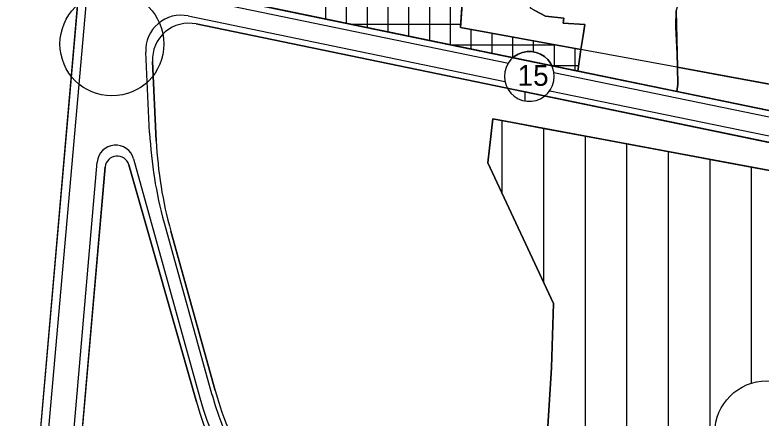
# Model space of a CAD drawing. Extents: x 427903 to 430077, y 4477233 to 4480385.
# Drawn here: x 428375.8 to 428734.8, y 4477497.4 to 4477691.4 of the extents above; entities that cross this region are included whole.
import ezdxf

# ---------------------------------------------------------------- set-up
doc = ezdxf.new("R2010")
doc.units = 0
for name, color, linetype in [('ADAKENARI', 7, 'Continuous'), ('KALDIRIM', 7, 'Continuous'), ('KD_DAIRE', 7, 'Continuous'), ('KD_KAV_DA', 7, 'Continuous'), ('KD_YGEN', 7, 'Continuous'), ('PL_K_TALI_IS_MRK', 7, 'Continuous'), ('PL_KON_MEV_150', 7, 'Continuous'), ('PL_SAY_ILKOGRETIM', 7, 'Continuous'), ('SM_DAIRE', 7, 'Continuous'), ('TR_AZYOGUNKONUT', 7, 'Continuous'), ('TR_ILKEGITIM', 7, 'Continuous'), ('TR_TALIISMERK', 7, 'Continuous')]:
    doc.layers.add(name, color=color, linetype=linetype)

msp = doc.modelspace()

# ---------------------------------------------------------------- linework, layer by layer
at = {"layer": 'ADAKENARI'}
for p, q in [((428590.12, 4477685.46), (428594.74, 4477750.3)), ((428408.85, 4477729.21), (428366.87, 4477249.22)), ((428847.06, 4477622.99), (428441.36, 4477706.89)), ((428463.01, 4477687.09), (428615.63, 4477655.53)), ((428860.4, 4477635.66), (428590.12, 4477685.46)), ((428443.79, 4477630.84), (428441.95, 4477669.09)), ((428615.63, 4477655.53), (428924.99, 4477591.56)), ((428621.21, 4477650.07), (428621.21, 4477654.39)), ((428605.75, 4477641.43), (428603.35, 4477620.21)), ((428857.27, 4477594.38), (428605.75, 4477641.43)), ((428393.23, 4477321.12), (428419.22, 4477618.28)), ((428430.55, 4477619.3), (428463.11, 4477505.16)), ((428603.35, 4477620.21), (428634.94, 4477552.53)), ((428472.13, 4477510.61), (428450.8, 4477587.3)), ((428634.94, 4477552.53), (428633.92, 4477521.77)), ((428633.92, 4477521.77), (428630.48, 4477467.61))]:
    msp.add_line(p, q, dxfattribs=at)
msp.add_lwpolyline([(428693.89, 4477693.57), (428694.48, 4477666.23), (428694.67, 4477657.98), (428694.17, 4477654.61), (428646.58, 4477664.45), (428649.9, 4477686.86), (428639.49, 4477687.53), (428639.8, 4477689.85), (428631.05, 4477690.89), (428623.78, 4477694.62)], dxfattribs=at)
for centre, radius, start, end in [((428459.46, 4477669.93), 17.53, 78.3166, 182.7499), ((428641.48, 4477640.33), 197.92, 182.7499, 195.5411), ((428424.98, 4477617.78), 5.78, 15.2172, 175.0016), ((428629.69, 4477554.43), 163.54, 195.5411, 255.6258), ((428626.98, 4477551.89), 170.41, 195.9184, 255.6258)]:
    msp.add_arc(centre, radius, start, end, dxfattribs=at)
at = {"layer": 'KALDIRIM'}
for p, q in [((428387.85, 4477443.16), (428412.89, 4477729.53)), ((428437.16, 4477704.69), (428613.16, 4477668.3)), ((428459.16, 4477690.95), (428611.51, 4477659.45)), ((428440.6, 4477634.76), (428438.74, 4477673.49)), ((428635.12, 4477663.75), (428849.48, 4477619.43)), ((428633.12, 4477654.98), (428925.59, 4477594.5)), ((428432.87, 4477622.2), (428464.81, 4477507.1)), ((428399.73, 4477441.27), (428415.42, 4477620.64)), ((428447.57, 4477591.44), (428470.59, 4477508.66))]:
    msp.add_line(p, q, dxfattribs=at)
for centre, radius, start, end in [((428455.72, 4477674.3), 17, 78.3166, 182.7499), ((428637.36, 4477644.22), 196.99, 182.7499, 195.5411), ((428424.28, 4477619.87), 8.9, 15.2172, 175.0016), ((428627.59, 4477552.28), 168.93, 195.5098, 255.6258), ((428627.63, 4477552.33), 162.99, 195.5411, 255.6258)]:
    msp.add_arc(centre, radius, start, end, dxfattribs=at)
at = {"layer": 'KD_DAIRE'}
for p, q in [((428616.04, 4477671.42), (428614.4, 4477669.93)), ((428616.04, 4477671.42), (428614.4, 4477669.93)), ((428617.92, 4477672.58), (428616.04, 4477671.42)), ((428617.92, 4477672.58), (428616.04, 4477671.42)), ((428619.99, 4477673.38), (428617.92, 4477672.58)), ((428619.99, 4477673.38), (428617.92, 4477672.58)), ((428622.16, 4477673.79), (428619.99, 4477673.38)), ((428622.16, 4477673.79), (428619.99, 4477673.38)), ((428624.38, 4477673.79), (428622.16, 4477673.79)), ((428624.38, 4477673.79), (428622.16, 4477673.79)), ((428626.56, 4477673.38), (428624.38, 4477673.79)), ((428626.56, 4477673.38), (428624.38, 4477673.79)), ((428628.62, 4477672.58), (428626.56, 4477673.38)), ((428628.62, 4477672.58), (428626.56, 4477673.38)), ((428630.5, 4477671.42), (428628.62, 4477672.58)), ((428630.5, 4477671.42), (428628.62, 4477672.58)), ((428632.14, 4477669.93), (428630.5, 4477671.42)), ((428632.14, 4477669.93), (428630.5, 4477671.42)), ((428613.07, 4477668.16), (428612.08, 4477666.18)), ((428613.07, 4477668.16), (428612.08, 4477666.18)), ((428614.4, 4477669.93), (428613.07, 4477668.16)), ((428614.4, 4477669.93), (428613.07, 4477668.16)), ((428633.47, 4477668.16), (428632.14, 4477669.93)), ((428633.47, 4477668.16), (428632.14, 4477669.93)), ((428634.46, 4477666.18), (428633.47, 4477668.16)), ((428634.46, 4477666.18), (428633.47, 4477668.16)), ((428611.48, 4477664.05), (428611.27, 4477661.84)), ((428611.48, 4477664.05), (428611.27, 4477661.84)), ((428612.08, 4477666.18), (428611.48, 4477664.05)), ((428612.08, 4477666.18), (428611.48, 4477664.05)), ((428635.07, 4477664.05), (428634.46, 4477666.18)), ((428635.07, 4477664.05), (428634.46, 4477666.18)), ((428635.27, 4477661.84), (428635.07, 4477664.05)), ((428635.27, 4477661.84), (428635.07, 4477664.05)), ((428611.27, 4477661.84), (428611.48, 4477659.64)), ((428611.27, 4477661.84), (428611.48, 4477659.64)), ((428635.07, 4477659.64), (428635.27, 4477661.84)), ((428635.07, 4477659.64), (428635.27, 4477661.84)), ((428635.27, 4477661.84), (428635.27, 4477661.84)), ((428635.27, 4477661.84), (428635.27, 4477661.84)), ((428611.48, 4477659.64), (428612.08, 4477657.51)), ((428611.48, 4477659.64), (428612.08, 4477657.51)), ((428612.08, 4477657.51), (428613.07, 4477655.52)), ((428612.08, 4477657.51), (428613.07, 4477655.52)), ((428633.47, 4477655.52), (428634.46, 4477657.51)), ((428633.47, 4477655.52), (428634.46, 4477657.51)), ((428634.46, 4477657.51), (428635.07, 4477659.64)), ((428634.46, 4477657.51), (428635.07, 4477659.64)), ((428613.07, 4477655.52), (428614.4, 4477653.76)), ((428613.07, 4477655.52), (428614.4, 4477653.76)), ((428614.4, 4477653.76), (428616.04, 4477652.26)), ((428614.4, 4477653.76), (428616.04, 4477652.26)), ((428630.5, 4477652.26), (428632.14, 4477653.76)), ((428630.5, 4477652.26), (428632.14, 4477653.76)), ((428632.14, 4477653.76), (428633.47, 4477655.52)), ((428632.14, 4477653.76), (428633.47, 4477655.52)), ((428616.04, 4477652.26), (428617.92, 4477651.1)), ((428616.04, 4477652.26), (428617.92, 4477651.1)), ((428617.92, 4477651.1), (428619.99, 4477650.3)), ((428617.92, 4477651.1), (428619.99, 4477650.3)), ((428619.99, 4477650.3), (428622.16, 4477649.89)), ((428619.99, 4477650.3), (428622.16, 4477649.89)), ((428622.16, 4477649.89), (428624.38, 4477649.89)), ((428622.16, 4477649.89), (428624.38, 4477649.89)), ((428624.38, 4477649.89), (428626.56, 4477650.3)), ((428624.38, 4477649.89), (428626.56, 4477650.3)), ((428626.56, 4477650.3), (428628.62, 4477651.1)), ((428626.56, 4477650.3), (428628.62, 4477651.1)), ((428628.62, 4477651.1), (428630.5, 4477652.26)), ((428628.62, 4477651.1), (428630.5, 4477652.26))]:
    msp.add_line(p, q, dxfattribs=at)
at = {"layer": 'KD_KAV_DA'}
msp.add_circle((428422.47, 4477677.46), 25, dxfattribs=at)
at = {"layer": 'PL_K_TALI_IS_MRK'}
for points in [[(428441.36, 4477706.89), (428646.58, 4477664.45), (428648.09, 4477674.78), (428590.12, 4477685.46), (428594.74, 4477750.3), (428634.75, 4477751.63), (428636.08, 4477763.84), (428674.99, 4477765.93), (428678.2, 4477753.08), (428763.81, 4477755.92), (428875.07, 4477746.86), (428860.4, 4477635.66), (428694.48, 4477666.23), (428694.67, 4477657.98)], [(428366.87, 4477249.22), (428408.85, 4477729.21)], [(428891.92, 4477420.61), (428878.39, 4477421.75), (428877.77, 4477465.86), (428888.48, 4477466.51), (428892.66, 4477466.82), (428893.57, 4477524.11), (428893.84, 4477540.99), (428894.12, 4477558.47), (428883.39, 4477557.49), (428886.38, 4477599.54), (428621.21, 4477654.38), (428621.21, 4477654.38), (428615.63, 4477655.53), (428463.01, 4477687.09)], [(428441.95, 4477669.09), (428443.79, 4477630.84)], [(428694.67, 4477657.98), (428694.17, 4477654.61), (428847.06, 4477622.99)], [(428630.48, 4477467.61), (428633.92, 4477521.77), (428634.94, 4477552.53), (428630.22, 4477562.63), (428610.22, 4477605.48), (428603.35, 4477620.21), (428605.75, 4477641.43), (428610.22, 4477640.59), (428630.22, 4477636.85), (428650.22, 4477633.11), (428670.22, 4477629.37), (428690.22, 4477625.63)], [(428690.22, 4477625.63), (428710.22, 4477621.89), (428730.22, 4477618.14), (428750.22, 4477614.4), (428770.22, 4477610.66), (428790.22, 4477606.92), (428810.22, 4477603.18), (428830.22, 4477599.44), (428850.22, 4477595.7), (428857.27, 4477594.38), (428851.24, 4477498.49), (428850.22, 4477498.5), (428839.52, 4477498.6), (428838.69, 4477488.35)], [(428419.22, 4477618.28), (428393.23, 4477321.12), (428408.87, 4477320.97), (428411.96, 4477335.09), (428452.28, 4477328.86), (428493.21, 4477322.54), (428483.34, 4477275.45), (428509.85, 4477272.85), (428505.83, 4477247.86)], [(428463.11, 4477505.16), (428430.55, 4477619.3)], [(428450.8, 4477587.3), (428472.13, 4477510.61)]]:
    msp.add_lwpolyline(points, dxfattribs=at)
for centre, radius, start, end in [((428459.46, 4477669.93), 17.53, 78.3166, 182.7499), ((428641.48, 4477640.33), 197.92, 182.7499, 195.5411), ((428424.98, 4477617.78), 5.78, 15.2172, 175.0016), ((428629.69, 4477554.43), 163.54, 195.5411, 255.6258), ((428626.98, 4477551.89), 170.41, 195.9184, 255.6258)]:
    msp.add_arc(centre, radius, start, end, dxfattribs=at)
at = {"layer": 'PL_KON_MEV_150'}
for points in [[(428648.09, 4477674.78), (428649.09, 4477681.58), (428649.9, 4477686.86), (428639.49, 4477687.53), (428639.8, 4477689.85), (428631.05, 4477690.89), (428625.57, 4477693.67), (428623.78, 4477694.62), (428629.92, 4477721.31), (428631.49, 4477729.18), (428633.6, 4477742.79), (428634.43, 4477748.66), (428634.75, 4477751.63), (428594.74, 4477750.3), (428590.12, 4477685.46), (428648.09, 4477674.78)], [(428693.89, 4477693.57), (428694.48, 4477666.23), (428711.71, 4477663.06), (428731.71, 4477659.37), (428751.71, 4477655.69)]]:
    msp.add_lwpolyline(points, dxfattribs=at)
msp.add_lwpolyline([(428857.27, 4477594.38), (428851.24, 4477498.49), (428839.52, 4477498.6), (428838.69, 4477488.35), (428855.47, 4477480.87), (428852.32, 4477379.82), (428847.13, 4477374.01), (428765.15, 4477379.18), (428757.18, 4477388.77), (428744.71, 4477386.69), (428724.03, 4477368.58), (428691.7, 4477357.89), (428668.48, 4477380.82), (428635.65, 4477394.31), (428637.38, 4477422.86), (428644.03, 4477428.66), (428637.63, 4477449.23), (428630.48, 4477467.61), (428633.92, 4477521.77), (428634.94, 4477552.53), (428603.35, 4477620.21), (428605.75, 4477641.43)], close=True, dxfattribs=at)
at = {"layer": 'PL_SAY_ILKOGRETIM'}
for points in [[(428625.57, 4477693.67), (428631.05, 4477690.89), (428639.8, 4477689.85), (428639.49, 4477687.53), (428649.9, 4477686.86), (428649.09, 4477681.58), (428648.09, 4477674.78), (428646.58, 4477664.45), (428694.17, 4477654.61), (428694.67, 4477657.98), (428694.48, 4477666.23)], [(428694.48, 4477666.23), (428694.32, 4477672.65), (428693.75, 4477685.63), (428693.89, 4477693.57)]]:
    msp.add_lwpolyline(points, dxfattribs=at)
at = {"layer": 'SM_DAIRE'}
msp.add_circle((428737.52, 4477490.34), 25, dxfattribs=at)
at = {"layer": 'TR_AZYOGUNKONUT'}
for p, q in [((428610.22, 4477605.48), (428610.22, 4477640.59)), ((428630.22, 4477562.63), (428630.22, 4477636.85)), ((428650.22, 4477388.32), (428650.22, 4477633.11)), ((428670.22, 4477379.1), (428670.22, 4477629.37)), ((428690.22, 4477359.36), (428690.22, 4477625.63)), ((428710.22, 4477364.01), (428710.22, 4477621.89)), ((428730.22, 4477514.26), (428730.22, 4477618.14))]:
    msp.add_line(p, q, dxfattribs=at)
for points in [[(428763.81, 4477755.92), (428678.2, 4477753.08), (428678.39, 4477752.31), (428691.89, 4477752.29), (428700.09, 4477751.33), (428710.89, 4477750.43), (428720.87, 4477749.84), (428733.52, 4477748.79), (428733.74, 4477745.65), (428734.17, 4477745.55), (428734.17, 4477741.2), (428730.29, 4477734.01), (428722.14, 4477721.74), (428725.06, 4477715.86), (428729.23, 4477707.26), (428717.2, 4477706.36), (428707.78, 4477705.66), (428697.15, 4477704.92), (428693.89, 4477693.57), (428693.75, 4477685.63), (428694.32, 4477672.65), (428694.48, 4477666.23), (428854.98, 4477636.65)], [(428441.36, 4477706.89), (428615.46, 4477670.88), (428616.04, 4477671.42), (428617.92, 4477672.58), (428619.99, 4477673.38), (428622.16, 4477673.79), (428624.38, 4477673.79), (428626.56, 4477673.38), (428628.62, 4477672.58), (428630.5, 4477671.42), (428632.14, 4477669.93), (428633.47, 4477668.16), (428634.03, 4477667.04), (428646.58, 4477664.45), (428648.09, 4477674.78), (428590.12, 4477685.46), (428594.74, 4477750.3)], [(428594.74, 4477750.3), (428590.12, 4477685.46), (428648.09, 4477674.78), (428649.09, 4477681.58), (428649.9, 4477686.86), (428639.49, 4477687.53), (428639.8, 4477689.85), (428631.05, 4477690.89), (428625.57, 4477693.67), (428623.78, 4477694.62), (428629.92, 4477721.31), (428631.49, 4477729.18), (428633.6, 4477742.79), (428634.43, 4477748.66), (428634.75, 4477751.63), (428594.74, 4477750.3)], [(428693.89, 4477693.57), (428694.48, 4477666.23), (428711.71, 4477663.06), (428731.71, 4477659.37), (428751.71, 4477655.69)], [(428691.7, 4477357.89), (428724.03, 4477368.58), (428744.71, 4477386.69), (428757.18, 4477388.77), (428765.15, 4477379.18), (428847.13, 4477374.01), (428852.32, 4477379.82), (428855.47, 4477480.87), (428838.69, 4477488.35), (428839.52, 4477498.6), (428851.24, 4477498.49), (428857.27, 4477594.38), (428605.75, 4477641.43), (428603.35, 4477620.21), (428634.94, 4477552.53), (428633.92, 4477521.77), (428630.48, 4477467.61), (428637.63, 4477449.23), (428644.03, 4477428.66), (428637.38, 4477422.86), (428635.65, 4477394.31), (428668.48, 4477380.82), (428691.7, 4477357.89)]]:
    msp.add_lwpolyline(points, dxfattribs=at)
at = {"layer": 'TR_ILKEGITIM'}
for p, q in [((428662.86, 4477672.3), (428662.86, 4477672.3)), ((428662.86, 4477672.3), (428662.86, 4477672.3)), ((428682.86, 4477672.3), (428682.86, 4477672.3)), ((428682.86, 4477672.3), (428682.86, 4477672.3))]:
    msp.add_line(p, q, dxfattribs=at)
at = {"layer": 'TR_TALIISMERK'}
for p, q in [((428535.33, 4477687.45), (428535.33, 4477920.37)), ((428545.33, 4477685.39), (428545.33, 4477918.52)), ((428555.33, 4477683.32), (428555.33, 4477916.66)), ((428565.33, 4477681.25), (428565.33, 4477914.81)), ((428575.33, 4477679.18), (428575.33, 4477912.95)), ((428585.33, 4477677.11), (428585.33, 4477911.09)), ((428525.33, 4477689.52), (428525.33, 4477813.49)), ((428590.22, 4477686.9), (428537.98, 4477686.9)), ((428595.33, 4477675.05), (428595.33, 4477684.5)), ((428605.33, 4477672.98), (428605.33, 4477682.66)), ((428615.33, 4477670.91), (428615.33, 4477680.82)), ((428625.33, 4477673.61), (428625.33, 4477678.97)), ((428636.56, 4477676.9), (428586.34, 4477676.9)), ((428635.33, 4477666.77), (428635.33, 4477677.13)), ((428645.33, 4477664.71), (428645.33, 4477675.29)), ((428646.94, 4477666.9), (428634.7, 4477666.9))]:
    msp.add_line(p, q, dxfattribs=at)
for points in [[(428441.36, 4477706.89), (428615.46, 4477670.88), (428616.04, 4477671.42), (428617.92, 4477672.58), (428619.99, 4477673.38), (428622.16, 4477673.79), (428624.38, 4477673.79), (428626.56, 4477673.38), (428628.62, 4477672.58), (428630.5, 4477671.42), (428632.14, 4477669.93), (428633.47, 4477668.16), (428634.03, 4477667.04), (428646.58, 4477664.45), (428648.09, 4477674.78), (428590.12, 4477685.46), (428594.74, 4477750.3)], [(428366.87, 4477249.22), (428408.85, 4477729.21)], [(428891.92, 4477420.61), (428878.39, 4477421.75), (428877.77, 4477465.86), (428888.48, 4477466.51), (428892.66, 4477466.82), (428893.57, 4477524.11), (428893.84, 4477540.99), (428894.12, 4477558.47), (428883.39, 4477557.49), (428886.38, 4477599.54), (428621.21, 4477654.38), (428621.21, 4477654.38), (428615.63, 4477655.53), (428463.01, 4477687.09)], [(428441.95, 4477669.09), (428443.79, 4477630.84)], [(428854.98, 4477636.65), (428851.71, 4477637.26), (428831.71, 4477640.94), (428811.71, 4477644.63), (428791.71, 4477648.31), (428771.71, 4477652), (428751.71, 4477655.69), (428731.71, 4477659.37), (428711.71, 4477663.06), (428694.48, 4477666.23), (428694.67, 4477657.98), (428694.17, 4477654.61), (428847.06, 4477622.99), (428848, 4477622.86)], [(428751.71, 4477655.69), (428731.71, 4477659.37), (428711.71, 4477663.06), (428694.48, 4477666.23), (428694.67, 4477657.98), (428694.17, 4477654.61), (428847.06, 4477622.99), (428848, 4477622.86)], [(428630.48, 4477467.61), (428633.92, 4477521.77), (428634.94, 4477552.53), (428630.22, 4477562.63), (428610.22, 4477605.48), (428603.35, 4477620.21), (428605.75, 4477641.43), (428610.22, 4477640.59), (428630.22, 4477636.85), (428650.22, 4477633.11), (428670.22, 4477629.37), (428690.22, 4477625.63), (428710.22, 4477621.89), (428730.22, 4477618.14), (428750.22, 4477614.4)], [(428419.22, 4477618.28), (428393.23, 4477321.12), (428408.87, 4477320.97), (428411.96, 4477335.09), (428452.28, 4477328.86), (428493.21, 4477322.54), (428483.34, 4477275.45), (428509.85, 4477272.85), (428505.83, 4477247.86)], [(428463.11, 4477505.16), (428430.55, 4477619.3)], [(428450.8, 4477587.3), (428472.13, 4477510.61)]]:
    msp.add_lwpolyline(points, dxfattribs=at)
for centre, radius, start, end in [((428459.46, 4477669.93), 17.53, 78.3166, 182.7499), ((428641.48, 4477640.33), 197.92, 182.7499, 195.5411), ((428424.98, 4477617.78), 5.78, 15.2172, 175.0016), ((428629.69, 4477554.43), 163.54, 195.5411, 255.6258), ((428626.98, 4477551.89), 170.41, 195.9184, 255.6258)]:
    msp.add_arc(centre, radius, start, end, dxfattribs=at)

# ---------------------------------------------------------------- texts
at = {"layer": 'KD_YGEN'}
msp.add_text('15', height=10, dxfattribs=at).set_placement((428617.66, 4477657.32))

doc.saveas('drawing.dxf')
